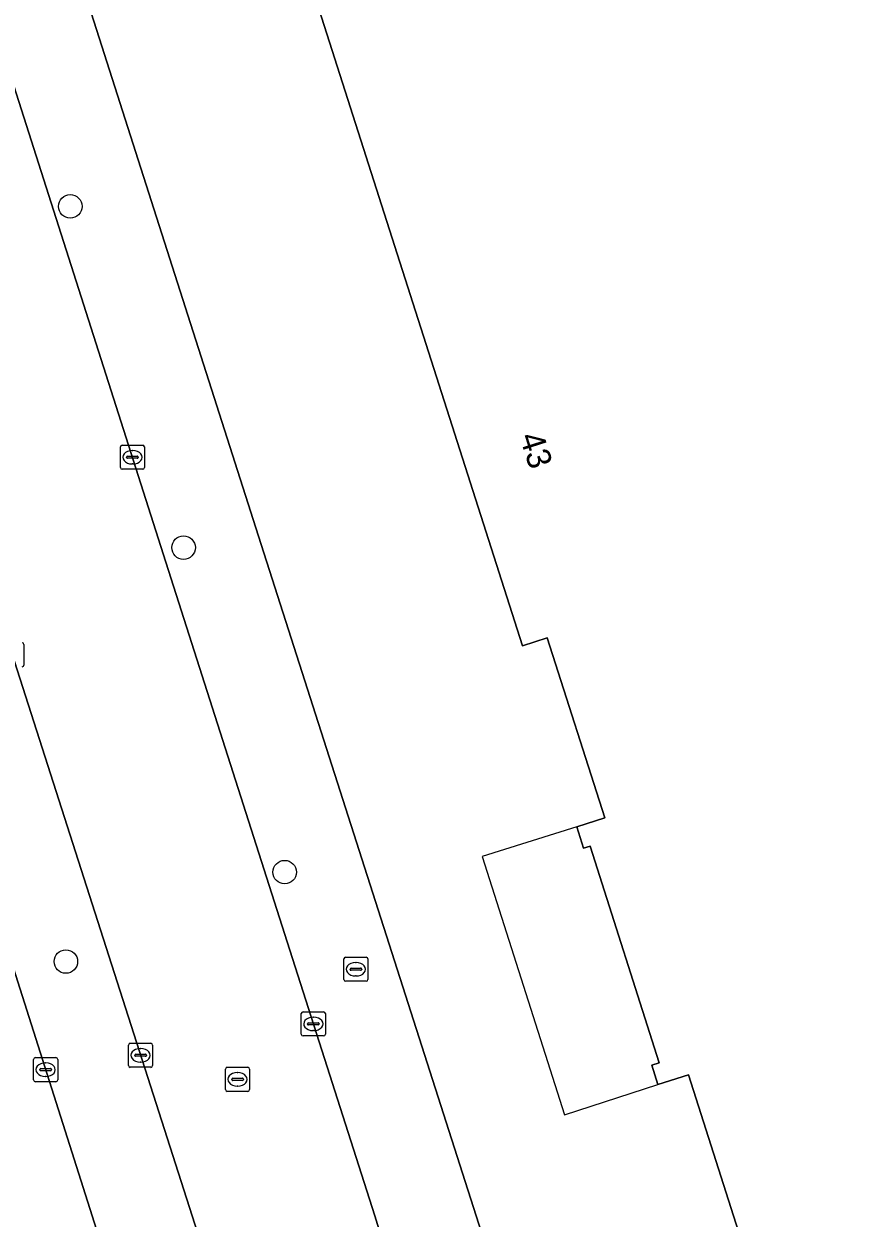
# Model space of a CAD drawing. Extents: x 159499 to 160349, y 382524 to 383273.
# Drawn here: x 159589.77 to 159624.25, y 382749.91 to 382799.52 of the extents above; entities that cross this region are included whole.
import ezdxf

# ---------------------------------------------------------------- set-up
doc = ezdxf.new("R2010")
doc.units = 0
for name, color, linetype in [('IMGEO_Berm_groen', 7, 'Continuous'), ('IMGEO_Boom', 7, 'Continuous'), ('IMGEO_Brandkraan', 7, 'Continuous'), ('IMGEO_Erf', 7, 'Continuous'), ('IMGEO_Kolk', 7, 'Continuous'), ('IMGEO_Pand', 7, 'Continuous'), ('IMGEO_Pand_nummerreeks', 7, 'Continuous'), ('IMGEO_Pand_overbouw', 7, 'Continuous'), ('IMGEO_Rijbaan_lokaal_open', 7, 'Continuous'), ('IMGEO_Rijbaan_regionaal_gesloten', 7, 'Continuous'), ('IMGEO_Rioolput', 7, 'Continuous'), ('IMGEO_Voetpad_open', 7, 'Continuous')]:
    doc.layers.add(name, color=color, linetype=linetype)

msp = doc.modelspace()

# ---------------------------------------------------------------- linework, layer by layer
at = {"layer": 'IMGEO_Berm_groen'}
for points in [[(159596.758, 382750), (159588.663, 382775.19), (159586.93, 382780.584), (159580.757, 382800.012), (159569.974, 382833.753), (159560.95, 382861.963), (159559.371, 382866.945), (159551.541, 382891.638), (159548.742, 382900.089), (159546.225, 382907.873), (159544.733, 382912.397)], [(159542.768, 382905.078), (159543.155, 382903.882), (159544.346, 382900.196), (159548.656, 382887.185), (159555.533, 382865.751), (159561.837, 382846.103), (159577.422, 382797.414), (159589.136, 382760.908), (159592.595, 382750), (159602.362, 382719.194), (159612.315, 382687.423), (159616.35, 382674.798)], [(159620.67, 382675.522), (159612.558, 382700.837), (159606.876, 382718.49), (159601.26, 382736.112), (159598.169, 382745.608), (159596.758, 382750)]]:
    msp.add_lwpolyline(points, dxfattribs=at)
at = {"layer": 'IMGEO_Boom'}
for centre in [(159591.691, 382791.944), (159596.397, 382777.766), (159600.596, 382764.285), (159591.509, 382760.569)]:
    msp.add_circle(centre, 0.489, dxfattribs=at)
at = {"layer": 'IMGEO_Brandkraan'}
for p, q in [((159603.127, 382760.75), (159603.979, 382760.75)), ((159603.052, 382759.824), (159603.052, 382760.676)), ((159603.311, 382760.244), (159603.311, 382760.256)), ((159603.749, 382760.207), (159603.351, 382760.207)), ((159603.354, 382760.293), (159603.752, 382760.293)), ((159603.54, 382760.53), (159603.565, 382760.53)), ((159603.795, 382760.256), (159603.795, 382760.244)), ((159604.053, 382760.676), (159604.053, 382759.824)), ((159603.979, 382759.75), (159603.127, 382759.75)), ((159603.563, 382759.97), (159603.538, 382759.97))]:
    msp.add_line(p, q, dxfattribs=at)
for points in [[(159603.127, 382760.75), (159603.979, 382760.75)], [(159603.052, 382759.824), (159603.052, 382760.676)], [(159604.053, 382760.676), (159604.053, 382759.824)], [(159603.979, 382759.75), (159603.127, 382759.75)]]:
    msp.add_lwpolyline(points, dxfattribs=at)
for centre, radius, start, end in [((159603.129, 382760.674), 0.0765, 91.552, 178.448), ((159603.129, 382760.674), 0.0765, 91.552, 178.448), ((159603.977, 382760.674), 0.0765, 1.552, 88.448), ((159603.977, 382760.674), 0.0765, 1.552, 88.448), ((159603.351, 382760.253), 0.0403, 85.8775, 175.7526), ((159603.348, 382760.243), 0.0366, 178.938, 274.7102), ((159603.752, 382760.25), 0.043, 264.8664, 352.4533), ((159603.756, 382760.255), 0.0386, 1.7309, 96.639), ((159603.129, 382759.826), 0.0765, 181.552, 268.448), ((159603.129, 382759.826), 0.0765, 181.552, 268.448), ((159603.977, 382759.826), 0.0765, 271.552, 358.448), ((159603.977, 382759.826), 0.0765, 271.552, 358.448)]:
    msp.add_arc(centre, radius, start, end, dxfattribs=at)
for centre, major_axis, ratio, start_param, end_param in [((159603.539, 382760.25), (-0.387, 0.002), 0.722429, 4.712389, 7.853982), ((159603.564, 382760.25), (-0.39, 0.002), 0.717154, 1.570796, 4.712389)]:
    msp.add_ellipse(centre, major_axis=major_axis, ratio=ratio, start_param=start_param, end_param=end_param, dxfattribs=at)
at = {"layer": 'IMGEO_Erf'}
for points in [[(159593.891, 382903.145), (159589.662, 382901.787), (159564.56, 382893.728), (159563.379, 382891.259), (159566.009, 382883.027), (159567.698, 382877.74), (159599.511, 382778.247), (159608.543, 382750), (159615.024, 382729.732), (159616.638, 382724.684), (159616.99, 382723.583)], [(159625.271, 382728.858), (159619.31, 382747.487), (159618.99, 382747.384), (159618.806, 382747.96), (159619.784, 382748.273), (159619.234, 382750), (159617.365, 382755.862), (159616.101, 382755.458), (159615.844, 382756.261), (159616.155, 382756.36), (159613.277, 382765.365), (159613.012, 382765.28), (159612.729, 382766.165), (159613.887, 382766.535), (159611.497, 382774.013), (159610.474, 382773.686), (159591.185, 382834.035)]]:
    msp.add_lwpolyline(points, dxfattribs=at)
at = {"layer": 'IMGEO_Kolk'}
for p, q in [((159593.773, 382781.095), (159593.773, 382781.947)), ((159593.848, 382782.021), (159594.7, 382782.021)), ((159594.075, 382781.564), (159594.473, 382781.564)), ((159594.261, 382781.801), (159594.286, 382781.801)), ((159594.774, 382781.947), (159594.774, 382781.095)), ((159594.032, 382781.515), (159594.032, 382781.527)), ((159594.47, 382781.478), (159594.072, 382781.478)), ((159594.284, 382781.241), (159594.259, 382781.241)), ((159594.516, 382781.527), (159594.516, 382781.515)), ((159594.7, 382781.021), (159593.848, 382781.021)), ((159589.765, 382773.739), (159589.765, 382772.887)), ((159601.286, 382757.555), (159601.286, 382758.407)), ((159601.361, 382758.481), (159602.213, 382758.481)), ((159601.774, 382758.261), (159601.799, 382758.261)), ((159602.287, 382758.407), (159602.287, 382757.555)), ((159601.545, 382757.975), (159601.545, 382757.987)), ((159601.983, 382757.938), (159601.585, 382757.938)), ((159601.588, 382758.024), (159601.986, 382758.024)), ((159602.029, 382757.987), (159602.029, 382757.975)), ((159602.213, 382757.481), (159601.361, 382757.481)), ((159601.797, 382757.701), (159601.772, 382757.701)), ((159594.11, 382756.249), (159594.11, 382757.101)), ((159594.185, 382757.175), (159595.037, 382757.175)), ((159594.598, 382756.955), (159594.623, 382756.955)), ((159595.111, 382757.101), (159595.111, 382756.249)), ((159590.168, 382755.652), (159590.168, 382756.504)), ((159590.243, 382756.578), (159591.095, 382756.578)), ((159590.656, 382756.358), (159590.681, 382756.358)), ((159591.169, 382756.504), (159591.169, 382755.652)), ((159594.369, 382756.669), (159594.369, 382756.681)), ((159594.807, 382756.632), (159594.409, 382756.632)), ((159594.412, 382756.718), (159594.81, 382756.718)), ((159594.621, 382756.395), (159594.596, 382756.395)), ((159594.853, 382756.681), (159594.853, 382756.669)), ((159590.427, 382756.072), (159590.427, 382756.084)), ((159590.865, 382756.035), (159590.467, 382756.035)), ((159590.47, 382756.121), (159590.868, 382756.121)), ((159590.679, 382755.798), (159590.654, 382755.798)), ((159590.911, 382756.084), (159590.911, 382756.072)), ((159595.037, 382756.175), (159594.185, 382756.175)), ((159591.095, 382755.578), (159590.243, 382755.578))]:
    msp.add_line(p, q, dxfattribs=at)
for points in [[(159593.773, 382781.095), (159593.773, 382781.947)], [(159593.848, 382782.021), (159594.7, 382782.021)], [(159594.774, 382781.947), (159594.774, 382781.095)], [(159594.7, 382781.021), (159593.848, 382781.021)], [(159589.765, 382773.739), (159589.765, 382772.887)], [(159601.286, 382757.555), (159601.286, 382758.407)], [(159601.361, 382758.481), (159602.213, 382758.481)], [(159602.287, 382758.407), (159602.287, 382757.555)], [(159602.213, 382757.481), (159601.361, 382757.481)], [(159594.11, 382756.249), (159594.11, 382757.101)], [(159594.185, 382757.175), (159595.037, 382757.175)], [(159595.111, 382757.101), (159595.111, 382756.249)], [(159590.168, 382755.652), (159590.168, 382756.504)], [(159590.243, 382756.578), (159591.095, 382756.578)], [(159591.169, 382756.504), (159591.169, 382755.652)], [(159595.037, 382756.175), (159594.185, 382756.175)], [(159591.095, 382755.578), (159590.243, 382755.578)]]:
    msp.add_lwpolyline(points, dxfattribs=at)
for centre, radius, start, end in [((159593.85, 382781.945), 0.0765, 91.552, 178.448), ((159593.85, 382781.945), 0.0765, 91.552, 178.448), ((159594.072, 382781.524), 0.0403, 85.8775, 175.7526), ((159594.477, 382781.526), 0.0386, 1.7309, 96.639), ((159594.698, 382781.945), 0.0765, 1.552, 88.448), ((159594.698, 382781.945), 0.0765, 1.552, 88.448), ((159593.85, 382781.097), 0.0765, 181.552, 268.448), ((159593.85, 382781.097), 0.0765, 181.552, 268.448), ((159594.069, 382781.514), 0.0366, 178.938, 274.7102), ((159594.473, 382781.521), 0.043, 264.8664, 352.4533), ((159594.698, 382781.097), 0.0765, 271.552, 358.448), ((159594.698, 382781.097), 0.0765, 271.552, 358.448), ((159589.689, 382773.737), 0.0765, 1.552, 88.448), ((159589.689, 382773.737), 0.0765, 1.552, 88.448), ((159589.689, 382772.889), 0.0765, 271.552, 358.448), ((159589.689, 382772.889), 0.0765, 271.552, 358.448), ((159601.363, 382758.405), 0.0765, 91.552, 178.448), ((159601.363, 382758.405), 0.0765, 91.552, 178.448), ((159602.211, 382758.405), 0.0765, 1.552, 88.448), ((159602.211, 382758.405), 0.0765, 1.552, 88.448), ((159601.585, 382757.984), 0.0403, 85.8775, 175.7526), ((159601.582, 382757.974), 0.0366, 178.938, 274.7102), ((159601.986, 382757.981), 0.043, 264.8664, 352.4533), ((159601.99, 382757.986), 0.0386, 1.7309, 96.639), ((159601.363, 382757.557), 0.0765, 181.552, 268.448), ((159601.363, 382757.557), 0.0765, 181.552, 268.448), ((159602.211, 382757.557), 0.0765, 271.552, 358.448), ((159602.211, 382757.557), 0.0765, 271.552, 358.448), ((159594.187, 382757.099), 0.0765, 91.552, 178.448), ((159594.187, 382757.099), 0.0765, 91.552, 178.448), ((159595.035, 382757.099), 0.0765, 1.552, 88.448), ((159595.035, 382757.099), 0.0765, 1.552, 88.448), ((159590.245, 382756.502), 0.0765, 91.552, 178.448), ((159590.245, 382756.502), 0.0765, 91.552, 178.448), ((159591.093, 382756.502), 0.0765, 1.552, 88.448), ((159591.093, 382756.502), 0.0765, 1.552, 88.448), ((159594.187, 382756.251), 0.0765, 181.552, 268.448), ((159594.187, 382756.251), 0.0765, 181.552, 268.448), ((159594.409, 382756.678), 0.0403, 85.8775, 175.7526), ((159594.406, 382756.668), 0.0366, 178.938, 274.7102), ((159594.81, 382756.675), 0.043, 264.8664, 352.4533), ((159594.814, 382756.68), 0.0386, 1.7309, 96.639), ((159595.035, 382756.251), 0.0765, 271.552, 358.448), ((159595.035, 382756.251), 0.0765, 271.552, 358.448), ((159590.467, 382756.081), 0.0403, 85.8775, 175.7526), ((159590.464, 382756.071), 0.0366, 178.938, 274.7102), ((159590.868, 382756.078), 0.043, 264.8664, 352.4533), ((159590.872, 382756.083), 0.0386, 1.7309, 96.639), ((159590.245, 382755.654), 0.0765, 181.552, 268.448), ((159590.245, 382755.654), 0.0765, 181.552, 268.448), ((159591.093, 382755.654), 0.0765, 271.552, 358.448), ((159591.093, 382755.654), 0.0765, 271.552, 358.448)]:
    msp.add_arc(centre, radius, start, end, dxfattribs=at)
for centre, major_axis, ratio, start_param, end_param in [((159594.26, 382781.521), (-0.387, 0.002), 0.722429, 4.712389, 7.853982), ((159594.285, 382781.521), (-0.39, 0.002), 0.717154, 1.570796, 4.712389), ((159601.773, 382757.981), (-0.387, 0.002), 0.722429, 4.712389, 7.853982), ((159601.798, 382757.981), (-0.39, 0.002), 0.717154, 1.570796, 4.712389), ((159594.597, 382756.675), (-0.387, 0.002), 0.722429, 4.712389, 7.853982), ((159594.622, 382756.675), (-0.39, 0.002), 0.717154, 1.570796, 4.712389), ((159590.655, 382756.078), (-0.387, 0.002), 0.722429, 4.712389, 7.853982), ((159590.68, 382756.078), (-0.39, 0.002), 0.717154, 1.570796, 4.712389)]:
    msp.add_ellipse(centre, major_axis=major_axis, ratio=ratio, start_param=start_param, end_param=end_param, dxfattribs=at)
at = {"layer": 'IMGEO_Pand'}
msp.add_lwpolyline([(159591.185, 382834.035), (159610.474, 382773.686), (159611.497, 382774.013), (159613.887, 382766.535), (159612.729, 382766.165), (159613.012, 382765.28), (159613.277, 382765.365), (159616.155, 382756.36), (159615.844, 382756.261), (159616.101, 382755.458), (159617.365, 382755.862), (159619.234, 382750), (159619.784, 382748.273), (159618.806, 382747.96), (159618.99, 382747.384), (159619.31, 382747.487), (159625.271, 382728.858)], dxfattribs=at)
at = {"layer": 'IMGEO_Pand_overbouw'}
msp.add_lwpolyline([(159612.729, 382766.165), (159608.803, 382764.934), (159612.213, 382754.204), (159616.101, 382755.458), (159615.844, 382756.261), (159616.155, 382756.36), (159613.277, 382765.365), (159613.012, 382765.28)], close=True, dxfattribs=at)
at = {"layer": 'IMGEO_Rijbaan_lokaal_open'}
for points in [[(159595.663, 382777.163), (159588.936, 382798.248), (159565.406, 382871.781), (159563.883, 382876.546), (159562.222, 382881.742), (159559.092, 382891.532), (159553.797, 382907.263), (159553.741, 382907.489), (159553.201, 382909.181), (159550.348, 382918.574), (159550.079, 382919.415), (159544.222, 382927.182), (159543.818, 382927.718), (159543.632, 382927.965), (159542.866, 382926.616), (159540.134, 382921.726)], [(159544.733, 382912.397), (159546.225, 382907.873), (159548.742, 382900.089), (159551.541, 382891.638), (159559.371, 382866.945), (159560.95, 382861.963), (159569.974, 382833.753), (159580.757, 382800.012), (159586.93, 382780.584), (159588.663, 382775.19), (159596.758, 382750), (159598.169, 382745.608), (159601.26, 382736.112), (159606.876, 382718.49), (159612.558, 382700.837), (159620.67, 382675.522)], [(159615.29, 382715.399), (159613.679, 382720.399), (159612.712, 382723.428), (159611.099, 382728.477), (159607.431, 382739.96), (159604.341, 382750), (159600.806, 382761.041), (159595.663, 382777.163)]]:
    msp.add_lwpolyline(points, dxfattribs=at)
at = {"layer": 'IMGEO_Rijbaan_regionaal_gesloten'}
msp.add_lwpolyline([(159616.35, 382674.798), (159612.315, 382687.423), (159602.362, 382719.194), (159592.595, 382750), (159589.136, 382760.908), (159577.422, 382797.414), (159561.837, 382846.103), (159555.533, 382865.751)], dxfattribs=at)
at = {"layer": 'IMGEO_Rioolput'}
for p, q in [((159598.139, 382755.25), (159598.139, 382756.102)), ((159598.214, 382756.176), (159599.066, 382756.176)), ((159598.627, 382755.956), (159598.652, 382755.956)), ((159599.14, 382756.102), (159599.14, 382755.25)), ((159598.398, 382755.67), (159598.398, 382755.682)), ((159598.836, 382755.633), (159598.438, 382755.633)), ((159598.441, 382755.719), (159598.839, 382755.719)), ((159598.65, 382755.396), (159598.625, 382755.396)), ((159598.882, 382755.682), (159598.882, 382755.67)), ((159599.066, 382755.176), (159598.214, 382755.176))]:
    msp.add_line(p, q, dxfattribs=at)
for points in [[(159598.139, 382755.25), (159598.139, 382756.102)], [(159598.214, 382756.176), (159599.066, 382756.176)], [(159599.14, 382756.102), (159599.14, 382755.25)], [(159599.066, 382755.176), (159598.214, 382755.176)]]:
    msp.add_lwpolyline(points, dxfattribs=at)
for centre, radius, start, end in [((159598.216, 382756.1), 0.0765, 91.552, 178.448), ((159598.216, 382756.1), 0.0765, 91.552, 178.448), ((159599.064, 382756.1), 0.0765, 1.552, 88.448), ((159599.064, 382756.1), 0.0765, 1.552, 88.448), ((159598.216, 382755.252), 0.0765, 181.552, 268.448), ((159598.216, 382755.252), 0.0765, 181.552, 268.448), ((159598.438, 382755.679), 0.0403, 85.8775, 175.7526), ((159598.435, 382755.669), 0.0366, 178.938, 274.7102), ((159598.839, 382755.676), 0.043, 264.8664, 352.4533), ((159598.843, 382755.681), 0.0386, 1.7309, 96.639), ((159599.064, 382755.252), 0.0765, 271.552, 358.448), ((159599.064, 382755.252), 0.0765, 271.552, 358.448)]:
    msp.add_arc(centre, radius, start, end, dxfattribs=at)
for centre, major_axis, ratio, start_param, end_param in [((159598.626, 382755.676), (-0.387, 0.002), 0.722429, 4.712389, 7.853982), ((159598.651, 382755.676), (-0.39, 0.002), 0.717154, 1.570796, 4.712389)]:
    msp.add_ellipse(centre, major_axis=major_axis, ratio=ratio, start_param=start_param, end_param=end_param, dxfattribs=at)
at = {"layer": 'IMGEO_Voetpad_open'}
msp.add_lwpolyline([(159611.099, 382728.477), (159615.024, 382729.732), (159608.543, 382750), (159599.511, 382778.247), (159567.698, 382877.74), (159563.883, 382876.546), (159565.406, 382871.781), (159588.936, 382798.248), (159595.663, 382777.163), (159600.806, 382761.041), (159604.341, 382750), (159607.431, 382739.96)], close=True, dxfattribs=at)

# ---------------------------------------------------------------- texts
at = {"layer": 'IMGEO_Pand_nummerreeks'}
msp.add_text('43', height=1, rotation=287.7251, dxfattribs=at).set_placement((159610.341, 382782.379))

doc.saveas('drawing.dxf')
